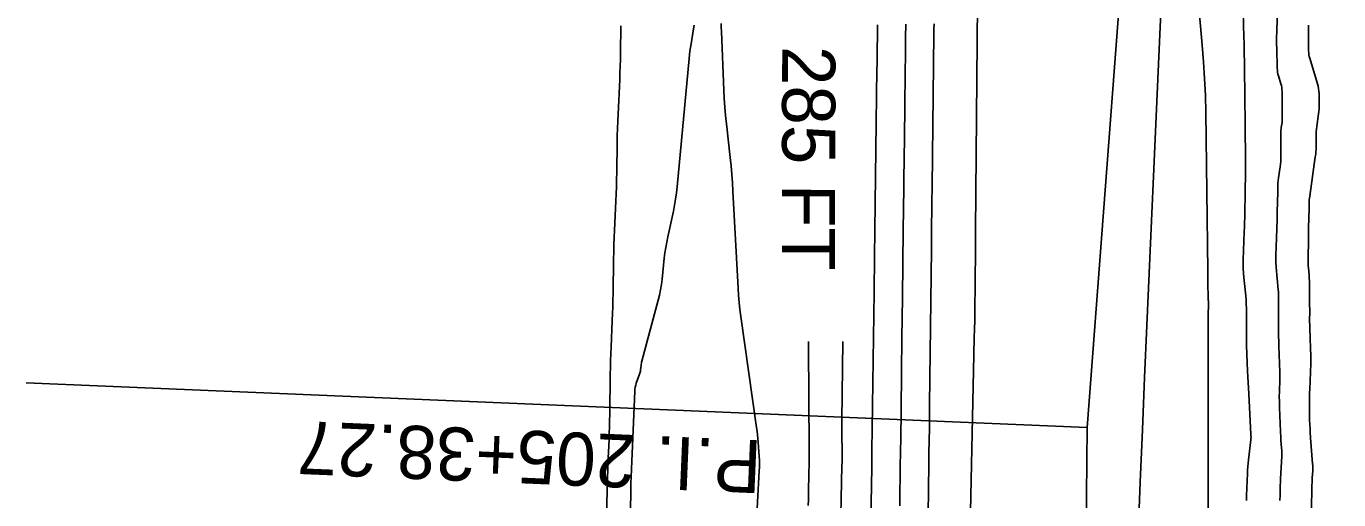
# Model space of a CAD drawing. Extents: x 1768942 to 1774819, y 723037 to 732099.
# Drawn here: x 1770407.9 to 1770556.2, y 730221.1 to 730274.7 of the extents above; entities that cross this region are included whole.
import ezdxf

# ---------------------------------------------------------------- set-up
doc = ezdxf.new("R2010")
doc.units = 0
for name, color, linetype in [('R_Contour Annot', 7, 'Continuous'), ('R_Contours', 7, 'Continuous'), ('R_Horz Alg', 7, 'Continuous'), ('R_Horz Alg Annot', 7, 'Continuous')]:
    doc.layers.add(name, color=color, linetype=linetype)

msp = doc.modelspace()

# ---------------------------------------------------------------- linework, layer by layer
at = {"layer": 'R_Contours'}
for points in [[(1770515.48, 730290.09), (1770515.14, 730251.54), (1770515.13, 730250.96), (1770515.13, 730250.39), (1770515.12, 730249.82), (1770515.12, 730249.24), (1770515.06, 730242.32), (1770515.06, 730241.92), (1770515.05, 730241.52), (1770515.04, 730241.11), (1770515.03, 730240.71), (1770514.97, 730239.1), (1770514.96, 730238.7), (1770514.95, 730238.3), (1770514.94, 730237.89), (1770514.93, 730237.49), (1770514.17, 730202.07)], [(1770541.43, 730199.53), (1770541.41, 730241.98), (1770541.41, 730242.03), (1770541.42, 730242.09), (1770541.42, 730242.15), (1770541.42, 730242.21), (1770541.43, 730242.48), (1770541.43, 730242.52), (1770541.43, 730242.57), (1770541.44, 730242.61), (1770541.44, 730242.66), (1770541.46, 730242.83), (1770541.47, 730242.88), (1770541.47, 730242.92), (1770541.47, 730242.97), (1770541.47, 730243.01), (1770541.44, 730243.46), (1770541.44, 730243.53), (1770541.44, 730243.6), (1770541.43, 730243.67), (1770541.43, 730243.74), (1770541.42, 730244.05), (1770541.42, 730244.1), (1770541.42, 730244.15), (1770541.42, 730244.2), (1770541.42, 730244.25), (1770541.42, 730244.45), (1770541.42, 730244.51), (1770541.41, 730244.56), (1770541.41, 730244.61), (1770541.41, 730244.66), (1770541.38, 730244.88), (1770541.38, 730244.94), (1770541.38, 730244.99), (1770541.38, 730245.05), (1770541.38, 730245.1), (1770541.39, 730245.44), (1770541.39, 730245.5), (1770541.39, 730245.56), (1770541.4, 730245.61), (1770541.4, 730245.67), (1770541.4, 730245.91), (1770541.4, 730245.96), (1770541.4, 730246.02), (1770541.4, 730246.07), (1770541.4, 730246.13), (1770541.4, 730246.34), (1770541.4, 730246.4), (1770541.4, 730246.45), (1770541.4, 730246.51), (1770541.4, 730246.56), (1770541.4, 730246.79), (1770541.4, 730246.84), (1770541.4, 730246.9), (1770541.4, 730246.95), (1770541.4, 730247.01), (1770541.14, 730264.92), (1770541.1, 730266.83), (1770541.02, 730268.73), (1770540.9, 730270.63), (1770540.75, 730272.53), (1770539.92, 730281.97)], [(1770549.53, 730221), (1770549.53, 730221.22), (1770549.54, 730221.44), (1770549.55, 730221.67), (1770549.57, 730222.57), (1770549.57, 730222.79), (1770549.58, 730223.02), (1770549.59, 730223.24), (1770549.6, 730223.46), (1770549.73, 730226.01), (1770549.74, 730226.25), (1770549.74, 730226.48), (1770549.74, 730226.71), (1770549.72, 730226.95), (1770549.65, 730227.88), (1770549.63, 730228.12), (1770549.62, 730228.35), (1770549.6, 730228.59), (1770549.59, 730228.82), (1770549.48, 730231.55), (1770549.48, 730231.71), (1770549.47, 730231.87), (1770549.47, 730232.02), (1770549.47, 730232.18), (1770549.46, 730232.82), (1770549.46, 730232.98), (1770549.47, 730233.13), (1770549.47, 730233.29), (1770549.48, 730233.45), (1770549.52, 730234.57), (1770549.53, 730234.81), (1770549.53, 730235.05), (1770549.53, 730235.29), (1770549.52, 730235.53), (1770549.42, 730238.47), (1770549.41, 730238.61), (1770549.41, 730238.75), (1770549.4, 730238.89), (1770549.4, 730239.03), (1770549.38, 730239.59), (1770549.38, 730239.73), (1770549.37, 730239.87), (1770549.37, 730240.01), (1770549.37, 730240.16), (1770549.38, 730242.42), (1770549.38, 730242.62), (1770549.38, 730242.82), (1770549.38, 730243.03), (1770549.38, 730243.23), (1770549.37, 730244.03), (1770549.37, 730244.24), (1770549.36, 730244.44), (1770549.35, 730244.64), (1770549.33, 730244.84), (1770549.11, 730247.4), (1770549.09, 730247.59), (1770549.08, 730247.78), (1770549.08, 730247.97), (1770549.08, 730248.16), (1770549.08, 730248.93), (1770549.08, 730249.12), (1770549.09, 730249.31), (1770549.09, 730249.5), (1770549.1, 730249.69), (1770549.2, 730252.75), (1770549.21, 730253.17), (1770549.22, 730253.58), (1770549.23, 730253.99), (1770549.24, 730254.41), (1770549.28, 730256.27), (1770549.29, 730256.58), (1770549.31, 730256.89), (1770549.34, 730257.2), (1770549.38, 730257.51), (1770549.55, 730258.75), (1770549.59, 730259.06), (1770549.62, 730259.37), (1770549.64, 730259.69), (1770549.64, 730260), (1770549.64, 730262.6), (1770549.65, 730262.75), (1770549.65, 730262.9), (1770549.67, 730263.05), (1770549.68, 730263.19), (1770549.77, 730263.78), (1770549.78, 730263.93), (1770549.79, 730264.07), (1770549.8, 730264.22), (1770549.8, 730264.37), (1770549.77, 730267.27), (1770549.76, 730267.49), (1770549.74, 730267.72), (1770549.69, 730267.94), (1770549.64, 730268.16), (1770549.37, 730269.03), (1770549.31, 730269.25), (1770549.27, 730269.47), (1770549.24, 730269.7), (1770549.22, 730269.92), (1770549.17, 730272.16), (1770549.16, 730272.61), (1770549.16, 730273.06), (1770549.16, 730273.51), (1770549.17, 730273.96), (1770549.24, 730277.17)], [(1770545.75, 730221.01), (1770545.77, 730221.56), (1770545.86, 730224.06), (1770545.88, 730224.45), (1770545.91, 730224.84), (1770545.94, 730225.23), (1770545.99, 730225.62), (1770546.25, 730227.89), (1770546.26, 730227.92), (1770546.26, 730227.95), (1770546.26, 730227.98), (1770546.26, 730228), (1770546.27, 730228.18), (1770546.27, 730228.18), (1770546.27, 730228.19), (1770546.26, 730228.37), (1770546.26, 730228.4), (1770546.26, 730228.43), (1770546.26, 730228.46), (1770546.26, 730228.49), (1770546.01, 730233.09), (1770545.97, 730233.73), (1770545.94, 730234.37), (1770545.91, 730235.01), (1770545.88, 730235.65), (1770545.77, 730238.56), (1770545.75, 730239.02), (1770545.74, 730239.49), (1770545.74, 730239.95), (1770545.74, 730240.42), (1770545.75, 730242.29), (1770545.74, 730242.75), (1770545.73, 730243.22), (1770545.7, 730243.68), (1770545.66, 730244.15), (1770545.45, 730246.24), (1770545.4, 730246.74), (1770545.38, 730247.24), (1770545.37, 730247.75), (1770545.38, 730248.25), (1770545.5, 730251.41), (1770545.52, 730251.95), (1770545.53, 730252.48), (1770545.55, 730253.01), (1770545.56, 730253.54), (1770545.61, 730255.73), (1770545.62, 730256.24), (1770545.62, 730256.74), (1770545.63, 730257.24), (1770545.63, 730257.74), (1770545.63, 730259.75), (1770545.63, 730260.25), (1770545.63, 730260.75), (1770545.63, 730261.25), (1770545.62, 730261.75), (1770545.6, 730263.85), (1770545.6, 730264.36), (1770545.59, 730264.88), (1770545.58, 730265.4), (1770545.58, 730265.91), (1770545.51, 730270.73), (1770545.5, 730271.4), (1770545.48, 730272.07), (1770545.47, 730272.74), (1770545.45, 730273.41), (1770545.36, 730276.27)], [(1770473.24, 730210.03), (1770473.5, 730222.27), (1770473.52, 730222.98), (1770473.54, 730223.68), (1770473.56, 730224.39), (1770473.59, 730225.1), (1770473.71, 730227.93), (1770473.74, 730228.63), (1770473.76, 730229.34), (1770473.78, 730230.05), (1770473.79, 730230.75), (1770473.85, 730235.3), (1770473.87, 730236.07), (1770473.89, 730236.83), (1770473.91, 730237.59), (1770473.94, 730238.35), (1770474.08, 730241.39), (1770474.11, 730242.15), (1770474.14, 730242.91), (1770474.16, 730243.67), (1770474.17, 730244.43), (1770474.22, 730248.32), (1770474.24, 730249.14), (1770474.26, 730249.96), (1770474.29, 730250.78), (1770474.32, 730251.6), (1770474.48, 730254.88), (1770474.51, 730255.69), (1770474.54, 730256.51), (1770474.56, 730257.33), (1770474.58, 730258.15), (1770474.62, 730261.44), (1770474.64, 730262.26), (1770474.66, 730263.08), (1770474.69, 730263.91), (1770474.73, 730264.73), (1770474.92, 730268.64), (1770474.95, 730269.4), (1770474.98, 730270.15), (1770475, 730270.91), (1770475.01, 730271.66), (1770475.06, 730274.69)], [(1770475.38, 730180), (1770476.17, 730222), (1770476.17, 730222.14), (1770476.17, 730222.28), (1770476.17, 730222.42), (1770476.18, 730222.56), (1770476.19, 730223.13), (1770476.19, 730223.27), (1770476.2, 730223.41), (1770476.2, 730223.55), (1770476.21, 730223.69), (1770476.63, 730233.39), (1770476.64, 730233.62), (1770476.68, 730233.84), (1770476.73, 730234.05), (1770476.79, 730234.27), (1770477.15, 730235.3), (1770477.19, 730235.42), (1770477.22, 730235.54), (1770477.25, 730235.66), (1770477.27, 730235.79), (1770477.33, 730236.29), (1770477.35, 730236.41), (1770477.37, 730236.54), (1770477.4, 730236.66), (1770477.43, 730236.78), (1770479.27, 730243.66), (1770479.41, 730244.25), (1770479.53, 730244.84), (1770479.63, 730245.43), (1770479.71, 730246.03), (1770479.96, 730248.43), (1770480.03, 730249.03), (1770480.12, 730249.63), (1770480.23, 730250.22), (1770480.35, 730250.82), (1770480.98, 730253.74), (1770481.12, 730254.42), (1770481.24, 730255.11), (1770481.34, 730255.8), (1770481.41, 730256.5), (1770482.76, 730271.01), (1770482.81, 730271.43), (1770482.86, 730271.85), (1770482.91, 730272.26), (1770482.98, 730272.68), (1770483.25, 730274.35), (1770483.32, 730274.77)], [(1770486.37, 730274.97), (1770486.39, 730274.51), (1770486.41, 730274.05), (1770486.68, 730267.42), (1770486.73, 730266.47), (1770486.79, 730265.51), (1770486.87, 730264.56), (1770486.97, 730263.61), (1770487.4, 730259.8), (1770487.5, 730258.85), (1770487.59, 730257.9), (1770487.66, 730256.94), (1770487.72, 730255.99), (1770488.31, 730245.02), (1770488.36, 730244.22), (1770488.43, 730243.41), (1770488.51, 730242.61), (1770488.62, 730241.81), (1770490.39, 730229.26), (1770490.44, 730228.85), (1770490.49, 730228.45), (1770490.53, 730228.04), (1770490.56, 730227.63), (1770490.68, 730226), (1770490.7, 730225.59), (1770490.71, 730225.18), (1770490.71, 730224.78), (1770490.69, 730224.37), (1770490.29, 730217.27)], [(1770503.2, 730213.79), (1770503.37, 730222.58), (1770503.38, 730222.92), (1770503.39, 730223.25), (1770503.39, 730223.59), (1770503.4, 730223.93), (1770503.41, 730225.27), (1770503.42, 730225.61), (1770503.42, 730225.95), (1770503.43, 730226.28), (1770503.43, 730226.62), (1770503.67, 730244.58), (1770503.68, 730245.16), (1770503.68, 730245.74), (1770503.69, 730246.32), (1770503.7, 730246.9), (1770503.72, 730249.22), (1770503.73, 730249.8), (1770503.74, 730250.38), (1770503.74, 730250.97), (1770503.75, 730251.55), (1770503.99, 730269.84), (1770504, 730270.34), (1770504.01, 730270.84), (1770504.01, 730271.34), (1770504.02, 730271.84), (1770504.04, 730273.83), (1770504.05, 730274.33), (1770504.05, 730274.83)], [(1770507.24, 730274.88), (1770507.23, 730273.41), (1770507.21, 730271.93), (1770507.14, 730266.04), (1770507.13, 730264.56), (1770507.11, 730263.09), (1770507.09, 730261.61), (1770507.07, 730260.14), (1770506.98, 730253.55), (1770506.96, 730252.02), (1770506.95, 730250.49), (1770506.93, 730248.96), (1770506.91, 730247.43), (1770506.84, 730241.28), (1770506.82, 730239.76), (1770506.8, 730238.24), (1770506.78, 730236.72), (1770506.76, 730235.21), (1770506.67, 730227.72), (1770506.65, 730226.91), (1770506.64, 730226.1), (1770506.63, 730225.29), (1770506.62, 730224.47), (1770506.58, 730221.18), (1770506.57, 730220.4)], [(1770509.74, 730216.6), (1770509.85, 730225.12), (1770509.86, 730225.68), (1770509.87, 730226.25), (1770509.87, 730226.81), (1770509.88, 730227.37), (1770509.91, 730229.62), (1770509.92, 730230.18), (1770509.93, 730230.74), (1770509.93, 730231.31), (1770509.94, 730231.87), (1770510.14, 730249.4), (1770510.15, 730250), (1770510.15, 730250.59), (1770510.16, 730251.18), (1770510.17, 730251.78), (1770510.2, 730254.15), (1770510.21, 730254.74), (1770510.21, 730255.34), (1770510.22, 730255.93), (1770510.23, 730256.52), (1770510.43, 730273.77), (1770510.43, 730274.35), (1770510.44, 730274.94)], [(1770553.08, 730219.75), (1770553.15, 730222.8), (1770553.16, 730223), (1770553.17, 730223.2), (1770553.17, 730223.4), (1770553.18, 730223.59), (1770553.23, 730224.38), (1770553.23, 730224.58), (1770553.23, 730224.78), (1770553.23, 730224.98), (1770553.22, 730225.17), (1770552.98, 730228.1), (1770552.97, 730228.31), (1770552.95, 730228.52), (1770552.94, 730228.72), (1770552.93, 730228.93), (1770552.9, 730229.77), (1770552.89, 730229.98), (1770552.89, 730230.18), (1770552.88, 730230.39), (1770552.88, 730230.6), (1770552.87, 730232.21), (1770552.87, 730232.54), (1770552.88, 730232.88), (1770552.89, 730233.22), (1770552.9, 730233.55), (1770553.01, 730236.52), (1770553.02, 730236.73), (1770553.02, 730236.95), (1770553.02, 730237.17), (1770553.02, 730237.39), (1770552.98, 730238.26), (1770552.98, 730238.48), (1770552.97, 730238.7), (1770552.96, 730238.92), (1770552.95, 730239.13), (1770552.9, 730240.78), (1770552.9, 730240.96), (1770552.89, 730241.14), (1770552.89, 730241.33), (1770552.89, 730241.51), (1770552.9, 730242.23), (1770552.9, 730242.41), (1770552.9, 730242.59), (1770552.9, 730242.77), (1770552.89, 730242.95), (1770552.86, 730245.67), (1770552.86, 730245.88), (1770552.85, 730246.08), (1770552.84, 730246.29), (1770552.82, 730246.5), (1770552.75, 730247.32), (1770552.73, 730247.52), (1770552.72, 730247.73), (1770552.72, 730247.94), (1770552.72, 730248.14), (1770552.74, 730250.79), (1770552.74, 730251.05), (1770552.75, 730251.31), (1770552.75, 730251.57), (1770552.76, 730251.83), (1770552.8, 730253), (1770552.8, 730253.2), (1770552.81, 730253.4), (1770552.82, 730253.6), (1770552.82, 730253.8), (1770552.83, 730254.61), (1770552.84, 730254.82), (1770552.85, 730255.02), (1770552.87, 730255.22), (1770552.9, 730255.42), (1770553.53, 730259.88), (1770553.57, 730260.17), (1770553.59, 730260.45), (1770553.61, 730260.74), (1770553.61, 730261.03), (1770553.62, 730262.17), (1770553.62, 730262.46), (1770553.64, 730262.74), (1770553.66, 730263.03), (1770553.69, 730263.31), (1770553.89, 730264.75), (1770553.92, 730265.03), (1770553.95, 730265.32), (1770553.96, 730265.6), (1770553.96, 730265.89), (1770553.95, 730267.04), (1770553.94, 730267.32), (1770553.9, 730267.6), (1770553.85, 730267.88), (1770553.78, 730268.16), (1770552.9, 730271.03), (1770552.84, 730271.23), (1770552.8, 730271.44), (1770552.78, 730271.65), (1770552.76, 730271.87), (1770552.74, 730272.73), (1770552.74, 730272.94), (1770552.74, 730273.16), (1770552.74, 730273.37), (1770552.74, 730273.59), (1770552.77, 730274.77)], [(1770496.26, 730239), (1770496.26, 730238.43), (1770496.33, 730226.88), (1770496.33, 730226.24), (1770496.33, 730225.6), (1770496.32, 730224.96), (1770496.31, 730224.31), (1770496.25, 730221.75), (1770496.24, 730221.1), (1770496.23, 730220.46)], [(1770499.83, 730215.66), (1770500.04, 730224.93), (1770500.05, 730225.36), (1770500.05, 730225.78), (1770500.05, 730226.21), (1770500.05, 730226.64), (1770500.04, 730228.34), (1770500.04, 730228.77), (1770500.04, 730229.2), (1770500.04, 730229.62), (1770500.04, 730230.05), (1770500.14, 730238.99)]]:
    msp.add_lwpolyline(points, dxfattribs=at)
at = {"layer": 'R_Horz Alg'}
for p, q in [((1770527.75, 730229.26), (1770556.18, 730606.87)), ((1770524.31, 729850.6), (1770527.75, 730229.26))]:
    msp.add_line(p, q, dxfattribs=at)
msp.add_lwpolyline([(1770527.75, 730229.26), (1770407.85, 730234.31)], dxfattribs=at)
msp.add_lwpolyline([(1770527.75, 730229.26), (1770407.85, 730234.31)], dxfattribs=at)
msp.add_arc((1781982.99, 729746.52), 11459.16, 175.694205, 179.479591, dxfattribs=at)

# ---------------------------------------------------------------- texts
at = {"layer": 'R_Contour Annot'}
msp.add_text('285 FT', height=6, rotation=269.9531, dxfattribs=at).set_placement((1770493.28, 730272.43))
at = {"layer": 'R_Horz Alg Annot'}
msp.add_text('P.I. 205+38.27', height=6, rotation=177.5869, dxfattribs=at).set_placement((1770491.05, 730227.81))
msp.add_text('P.I. 205+38.27', height=6, rotation=177.5869, dxfattribs=at).set_placement((1770491.05, 730227.81))

doc.saveas('drawing.dxf')
